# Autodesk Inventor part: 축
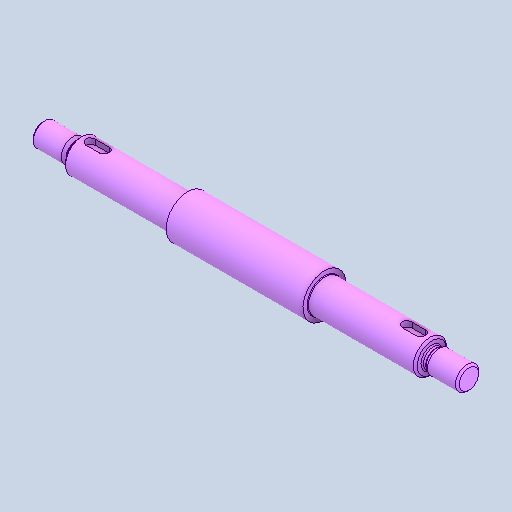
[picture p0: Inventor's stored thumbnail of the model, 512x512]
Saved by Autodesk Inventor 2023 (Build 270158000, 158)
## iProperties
Created: 2025-03
Part Number: 축
Material: 강철, 탄소
Document SubType Name: Modeling
Designer: ADMIN_PC
Density: 7.85 g/cm^3
Appearance: 기본값
Author: jhkim
Sending System: Autodesk Inventor 2025
Preprocessor: ST-DEVELOPER v20
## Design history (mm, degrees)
feature "솔리드1"
node "솔리드2"
